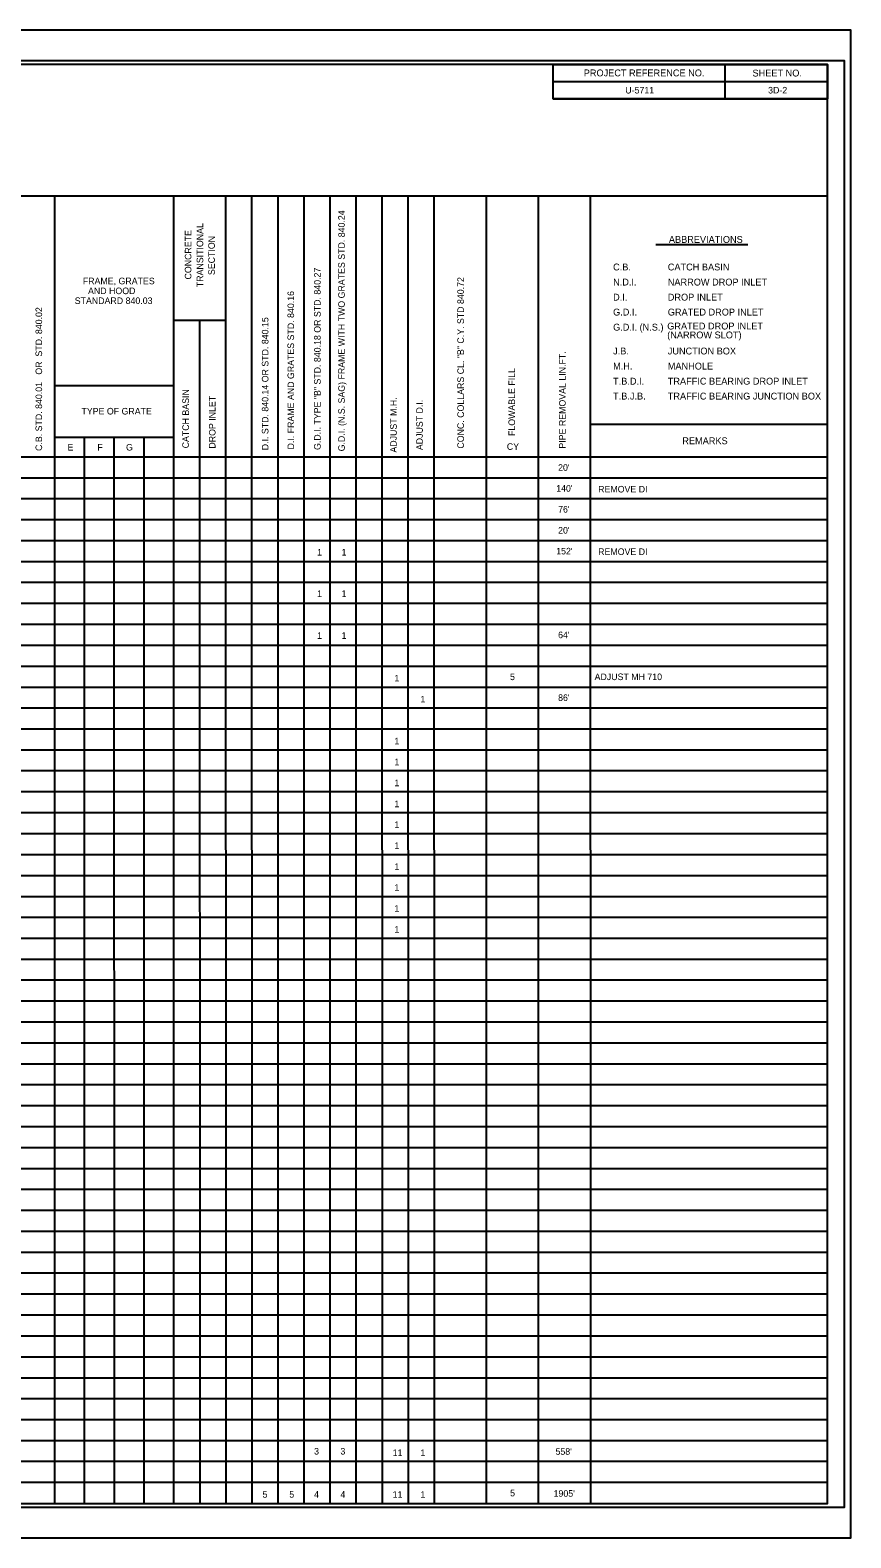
# Model space of a CAD drawing. Extents: x 1912419 to 1914138, y 231793 to 234289.
# Drawn here: x 1913505 to 1914103, y 231793 to 232893 of the extents above; entities that cross this region are included whole.
import ezdxf

# ---------------------------------------------------------------- set-up
doc = ezdxf.new("R2010")
doc.units = 0
for name, color, linetype in [('Sheet Cutting Line CELL', 7, 'Continuous'), ('Sheet Pipe Summary CELL', 7, 'Continuous'), ('Sheet Pipe Summary Grid CELL', 7, 'Continuous'), ('Sheet Plot Border Inside CELL', 7, 'Continuous'), ('Sheet Plot Border Outside CELL', 7, 'Continuous'), ('Sheet Summary Combination CELL', 7, 'Continuous')]:
    doc.layers.add(name, color=color, linetype=linetype)

msp = doc.modelspace()

# ---------------------------------------------------------------- linework, layer by layer
at = {"layer": 'Sheet Cutting Line CELL'}
for p, q in [((1914103.4, 232892.5), (1912419.4, 232892.5)), ((1912419.4, 231792.5), (1914103.4, 231792.5)), ((1912419.4, 231792.5), (1914103.4, 231792.5))]:
    msp.add_line(p, q, dxfattribs=at)
at = {"layer": 'Sheet Pipe Summary CELL'}
for p, q in [((1914011.4, 232867.5), (1914011.4, 232842.5)), ((1914011.4, 232867.5), (1914011.4, 232842.5)), ((1913886.4, 232855), (1914086.4, 232855)), ((1913886.4, 232855), (1914086.4, 232855)), ((1913886.4, 232842.5), (1914086.4, 232842.5)), ((1913886.4, 232842.5), (1914086.4, 232842.5)), ((1913886.4, 232842.5), (1914086.4, 232842.5)), ((1914028.2, 232735.9), (1913961.2, 232735.9))]:
    msp.add_line(p, q, dxfattribs=at)
for points in [[(1914086.4, 232867.5), (1912586.4, 232867.5), (1912586.4, 231817.5), (1914086.4, 231817.5)], [(1913886.4, 232867.5), (1914086.4, 232867.5), (1914086.4, 232842.5), (1913886.4, 232842.5)], [(1913886.4, 232867.5), (1914086.4, 232867.5), (1914086.4, 232842.5), (1913886.4, 232842.5)]]:
    msp.add_lwpolyline(points, close=True, dxfattribs=at)
at = {"layer": 'Sheet Pipe Summary Grid CELL'}
for p, q in [((1914086.4, 232771.4), (1912586.4, 232771.3)), ((1913522.7, 231817.6), (1913522.7, 232771.4)), ((1913609.7, 231817.6), (1913609.6, 232771.4)), ((1913647.7, 231817.4), (1913647.6, 232771.4)), ((1913666.7, 231817.4), (1913666.6, 232771.4)), ((1913685.7, 231817.4), (1913685.6, 232771.4)), ((1913704.7, 231817.4), (1913704.6, 232771.4)), ((1913723.7, 231817.4), (1913723.6, 232771.4)), ((1913742.7, 231817.4), (1913742.6, 232771.4)), ((1913761.7, 231817.4), (1913761.6, 232771.4)), ((1913780.7, 231817.4), (1913780.6, 232771.4)), ((1913799.7, 231817.4), (1913799.6, 232771.4)), ((1913799.7, 231817.4), (1913799.6, 232771.4)), ((1913837.7, 231817.4), (1913837.6, 232771.4)), ((1913837.7, 231817.4), (1913837.6, 232771.4)), ((1913875.7, 231817.4), (1913875.6, 232771.4)), ((1913913.7, 231817.4), (1913913.6, 232771.4)), ((1913647.6, 232680.7), (1913609.6, 232680.7)), ((1913628.7, 231817.4), (1913628.6, 232680.7)), ((1913609.6, 232633.1), (1913522.7, 232633.1)), ((1913609.6, 232595.3), (1913522.7, 232595.3)), ((1913544.5, 231817.6), (1913544.4, 232595.3)), ((1913566.2, 231817.6), (1913566.1, 232595.3)), ((1913587.9, 231817.6), (1913587.9, 232595.3)), ((1914086.4, 232604.8), (1913913.7, 232604.8)), ((1914086.4, 232581), (1912586.4, 232581)), ((1914086.4, 232565.7), (1912586.4, 232565.7)), ((1914086.4, 232550.5), (1912586.4, 232550.5)), ((1914086.4, 232535.2), (1912586.4, 232535.2)), ((1914086.4, 232519.9), (1912586.4, 232519.9)), ((1914086.4, 232504.7), (1912586.4, 232504.7)), ((1914086.4, 232489.4), (1912586.4, 232489.4)), ((1914086.4, 232474.1), (1912586.4, 232474.1)), ((1914086.4, 232458.9), (1912586.4, 232458.9)), ((1914086.4, 232443.6), (1912586.4, 232443.6)), ((1914086.4, 232428.3), (1912586.4, 232428.3)), ((1914086.4, 232413), (1912586.4, 232413)), ((1914086.4, 232397.8), (1912586.4, 232397.8)), ((1914086.4, 232382.5), (1912586.4, 232382.5)), ((1914086.4, 232367.2), (1912586.4, 232367.2)), ((1914086.4, 232352), (1912586.4, 232352)), ((1914086.4, 232336.7), (1912586.4, 232336.7)), ((1914086.4, 232321.4), (1912586.4, 232321.4)), ((1914086.4, 232306.2), (1912586.4, 232306.2)), ((1914086.4, 232290.9), (1912586.4, 232290.9)), ((1914086.4, 232275.6), (1912586.4, 232275.6)), ((1914086.4, 232260.3), (1912586.4, 232260.3)), ((1914086.4, 232245.1), (1912586.4, 232245.1)), ((1914086.4, 232229.8), (1912586.4, 232229.8)), ((1914086.4, 232214.5), (1912586.4, 232214.5)), ((1914086.4, 232199.3), (1912586.4, 232199.3)), ((1914086.4, 232184), (1912586.4, 232184)), ((1914086.4, 232168.7), (1912586.4, 232168.7)), ((1914086.4, 232153.5), (1912586.4, 232153.5)), ((1914086.4, 232138.2), (1912586.4, 232138.2)), ((1914086.4, 232122.9), (1912586.4, 232122.9)), ((1914086.4, 232107.6), (1912586.4, 232107.6)), ((1914086.4, 232092.4), (1912586.4, 232092.4)), ((1914086.4, 232077.1), (1912586.4, 232077.1)), ((1914086.4, 232061.8), (1912586.4, 232061.8)), ((1914086.4, 232046.6), (1912586.4, 232046.6)), ((1914086.4, 232031.3), (1912586.4, 232031.3)), ((1914086.4, 232016), (1912586.4, 232016)), ((1914086.4, 232000.8), (1912586.4, 232000.8)), ((1914086.4, 231985.5), (1912586.4, 231985.5)), ((1914086.4, 231970.2), (1912586.4, 231970.2)), ((1914086.4, 231954.9), (1912586.4, 231954.9)), ((1914086.4, 231939.7), (1912586.4, 231939.7)), ((1914086.4, 231924.4), (1912586.4, 231924.4)), ((1914086.4, 231909.1), (1912586.4, 231909.1)), ((1914086.4, 231893.9), (1912586.4, 231893.9)), ((1914086.4, 231878.6), (1912586.4, 231878.6)), ((1914086.4, 231863.3), (1912586.4, 231863.3)), ((1914086.4, 231848.1), (1912586.4, 231848.1)), ((1914086.4, 231832.8), (1912586.4, 231832.8))]:
    msp.add_line(p, q, dxfattribs=at)
at = {"layer": 'Sheet Plot Border Inside CELL'}
msp.add_lwpolyline([(1912432.4, 231815), (1914098.9, 231815), (1914098.9, 232870.1), (1912432.4, 232870.1)], close=True, dxfattribs=at)
at = {"layer": 'Sheet Plot Border Outside CELL'}
msp.add_lwpolyline([(1912419.4, 231792.5), (1914103.4, 231792.5), (1914103.4, 232892.5), (1912419.4, 232892.5)], close=True, dxfattribs=at)

# ---------------------------------------------------------------- texts
at = {"layer": 'Sheet Pipe Summary CELL'}
for s, height, p in [('PROJECT REFERENCE NO.', 5, (1913908.6, 232858.8)), ('PROJECT REFERENCE NO.', 5, (1913908.6, 232858.8)), ('SHEET NO.', 5, (1914031.7, 232858.7)), ('SHEET NO.', 5, (1914031.7, 232858.7)), ('ABBREVIATIONS', 5, (1913970.7, 232737.3)), ('C.B.', 5, (1913930, 232717.2)), ('CATCH BASIN', 5, (1913969.9, 232717.2)), ('FRAME, GRATES', 4.8, (1913543.2, 232707.1)), ('N.D.I.', 5, (1913930, 232706.2)), ('NARROW DROP INLET', 5, (1913969.9, 232706.2)), ('STANDARD 840.03', 4.8, (1913537.3, 232692.7)), ('AND HOOD', 4.8, (1913547, 232699.9)), ('D.I.', 5, (1913930, 232695.2)), ('DROP INLET', 5, (1913969.9, 232695.2)), ('G.D.I.', 5, (1913930, 232684.3)), ('GRATED DROP INLET', 5, (1913969.9, 232684.3)), ('G.D.I. (N.S.)', 5, (1913930, 232673.3)), ('J.B.', 5, (1913930, 232655.9)), ('JUNCTION BOX', 5, (1913969.9, 232655.9)), ('M.H.', 5, (1913930, 232644.9)), ('TRAFFIC BEARING DROP INLET', 5, (1913969.9, 232633.9)), ('MANHOLE', 5, (1913969.9, 232644.9)), ('T.B.D.I.', 5, (1913930, 232633.9)), ('TRAFFIC BEARING JUNCTION BOX', 5, (1913969.9, 232623)), ('T.B.J.B.', 5, (1913930, 232623)), ('TYPE OF GRATE', 4.8, (1913542.2, 232612.1)), ('REMARKS', 5, (1913980.5, 232590.4)), ('E', 4.8, (1913532, 232585.8)), ('F', 4.8, (1913553.8, 232585.8)), ('G', 4.8, (1913574.7, 232585.8))]:
    msp.add_text(s, height=height, dxfattribs=at).set_placement(p)
for s, height, rotation, p in [('G.D.I. (N.S. SAG) FRAME WITH TWO GRATES STD. 840.24', 4.8, 90, (1913734.3, 232585.2)), ('TRANSITIONAL', 4.8, 90, (1913631, 232705)), ('CONCRETE', 4.8, 90, (1913622.4, 232710.6)), ('SECTION', 4.8, 90, (1913639.5, 232713.8)), ('G.D.I. TYPE "B" STD. 840.18 OR STD. 840.27', 4.8, 90, (1913716.7, 232586.2)), ('CONC. COLLARS CL. "B" C.Y. STD 840.72', 4.8, 90, (1913821.2, 232587.2)), ('D.I. FRAME AND GRATES STD. 840.16', 4.8, 90, (1913697.3, 232586.6)), ('C.B. STD. 840.01   OR  STD. 840.02', 4.8, 90, (1913513.5, 232585.5)), ('D.I. STD. 840.14 OR STD. 840.15', 4.8, 90, (1913678.6, 232586)), ('GRATED DROP INLET', 5, 0.0274, (1913969.5, 232674.1)), ('(NARROW SLOT)', 5, 0.0274, (1913969.5, 232667.6)), ('PIPE REMOVAL LIN.FT.', 4.8, 90, (1913895.4, 232587.2)), ('FLOWABLE FILL', 4.8, 90, (1913858.5, 232596.4)), ('CATCH BASIN', 4.8, 90, (1913620.6, 232587.4)), ('DROP INLET', 4.8, 90, (1913640, 232587.2)), ('ADJUST M.H.', 4.8, 90, (1913772.2, 232584.3)), ('ADJUST D.I.', 4.8, 90, (1913791.2, 232586.1))]:
    msp.add_text(s, height=height, rotation=rotation, dxfattribs=at).set_placement(p)
at = {"layer": 'Sheet Summary Combination CELL'}
for s, p in [('U-5711', (1913938.9, 232846.3)), ('3D-2', (1914043.1, 232846.3)), ('CY', (1913852.5, 232586.3)), ("20'", (1913889.9, 232571)), ("140'", (1913888.5, 232555.8)), ('REMOVE DI', (1913919.1, 232555.2)), ("76'", (1913889.9, 232540.5)), ("20'", (1913889.9, 232525.2)), ('1', (1913714.1, 232509.2)), ('1', (1913731.9, 232509.2)), ("152'", (1913888.5, 232510)), ('REMOVE DI', (1913919.1, 232509.6)), ('1', (1913714.1, 232479)), ('1', (1913731.9, 232479)), ('1', (1913714.1, 232448.4)), ('1', (1913731.9, 232448.4)), ("64'", (1913889.9, 232448.9)), ('1', (1913770.5, 232417.3)), ('5', (1913854.8, 232418.3)), ('5', (1913854.8, 232418.3)), ('ADJUST MH 710', (1913916.5, 232418.3)), ('1', (1913789.5, 232402)), ("86'", (1913889.9, 232403.1)), ('1', (1913770.5, 232371.4)), ('1', (1913770.5, 232356.2)), ('1', (1913770.5, 232340.9)), ('1', (1913770.5, 232325.6)), ('1', (1913770.5, 232310.4)), ('1', (1913770.5, 232295.1)), ('1', (1913770.5, 232279.8)), ('1', (1913770.5, 232264.6)), ('1', (1913770.5, 232249.3)), ('1', (1913770.5, 232234)), ('3', (1913711.9, 231853.3)), ('3', (1913731.1, 231853.3)), ('11', (1913769.2, 231852.2)), ('1', (1913789.5, 231852.2)), ("558'", (1913888, 231853.1)), ("558'", (1913888, 231853.1)), ('5', (1913674.3, 231821.8)), ('5', (1913693.8, 231821.8)), ('4', (1913711.9, 231821.8)), ('4', (1913731.1, 231821.8)), ('11', (1913769.2, 231821.7)), ('1', (1913789.5, 231821.7)), ('5', (1913854.9, 231822.8)), ('5', (1913854.9, 231822.8)), ("1905'", (1913886.6, 231822.5)), ("1905'", (1913886.6, 231822.5))]:
    msp.add_text(s, height=4.8, dxfattribs=at).set_placement(p)

doc.saveas('drawing.dxf')
